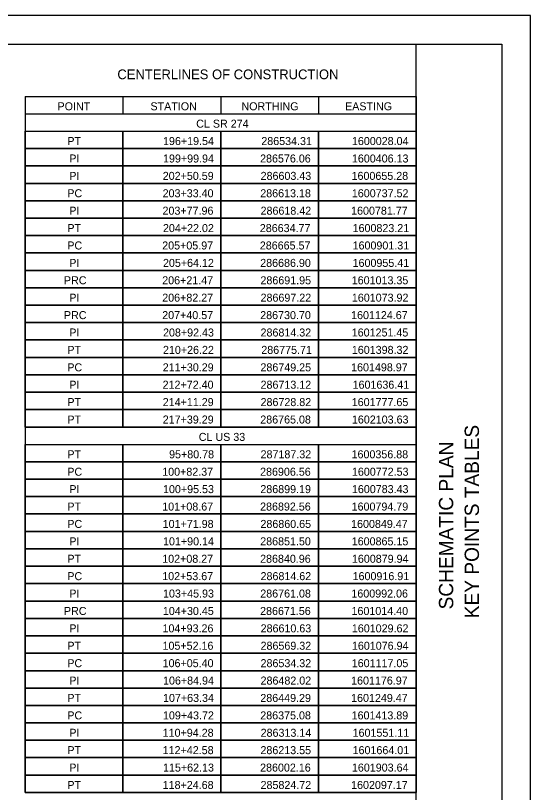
# Model space of a CAD drawing. Extents: x 0 to 34, y 0 to 22.
# Drawn here: x 25 to 34, y 8.41 to 22 of the extents above; entities that cross this region are included whole.
import ezdxf

# ---------------------------------------------------------------- set-up
doc = ezdxf.new("R2010")
doc.units = 0
for name, color, linetype in [('SH_Border', 7, 'Continuous'), ('SH_Cut_Line', 7, 'Continuous'), ('SH_Data', 7, 'Continuous'), ('SH_Text', 7, 'Continuous')]:
    doc.layers.add(name, color=color, linetype=linetype)

msp = doc.modelspace()

# ---------------------------------------------------------------- linework, layer by layer
at = {"layer": 'SH_Border'}
msp.add_line((32, 0.5), (32, 21.5), dxfattribs=at)
msp.add_lwpolyline([(1.5, 21.5), (33.5, 21.5), (33.5, 0.5), (1.5, 0.5)], close=True, dxfattribs=at)
at = {"layer": 'SH_Cut_Line'}
msp.add_lwpolyline([(0, 0), (34, 0), (34, 22), (0, 22)], close=True, dxfattribs=at)
at = {"layer": 'SH_Text'}
for p, q in [((25.169, 20.587), (32, 20.587)), ((25.169, 20.587), (25.169, 19.978)), ((26.877, 20.587), (26.877, 20.283)), ((28.585, 20.587), (28.585, 20.283)), ((30.292, 20.587), (30.292, 20.283)), ((32, 20.587), (32, 19.978)), ((25.169, 20.283), (32, 20.283)), ((25.169, 19.978), (32, 19.978)), ((25.169, 19.978), (25.169, 14.804)), ((26.877, 19.978), (26.877, 14.804)), ((28.585, 19.978), (28.585, 14.804)), ((30.292, 19.978), (30.292, 14.804)), ((32, 19.978), (32, 14.804)), ((25.169, 19.674), (32, 19.674)), ((25.169, 19.37), (32, 19.37)), ((25.169, 19.065), (32, 19.065)), ((25.169, 18.761), (32, 18.761)), ((25.169, 18.457), (32, 18.457)), ((25.169, 18.152), (32, 18.152)), ((25.169, 17.848), (32, 17.848)), ((25.169, 17.543), (32, 17.543)), ((25.169, 17.239), (32, 17.239)), ((25.169, 16.935), (32, 16.935)), ((25.169, 16.63), (32, 16.63)), ((25.169, 16.326), (32, 16.326)), ((25.169, 16.022), (32, 16.022)), ((25.169, 15.717), (32, 15.717)), ((25.169, 15.413), (32, 15.413)), ((25.169, 15.109), (32, 15.109)), ((25.169, 14.804), (32, 14.804)), ((25.169, 14.804), (25.169, 14.5)), ((32, 14.804), (32, 14.5)), ((25.169, 14.5), (32, 14.5)), ((25.169, 14.5), (25.169, 8.413)), ((26.877, 14.5), (26.877, 8.413)), ((28.585, 14.5), (28.585, 8.413)), ((30.292, 14.5), (30.292, 8.413)), ((32, 14.5), (32, 8.413)), ((25.169, 14.196), (32, 14.196)), ((25.169, 13.891), (32, 13.891)), ((25.169, 13.587), (32, 13.587)), ((25.169, 13.283), (32, 13.283)), ((25.169, 12.978), (32, 12.978)), ((25.169, 12.674), (32, 12.674)), ((25.169, 12.37), (32, 12.37)), ((25.169, 12.065), (32, 12.065)), ((25.169, 11.761), (32, 11.761)), ((25.169, 11.457), (32, 11.457)), ((25.169, 11.152), (32, 11.152)), ((25.169, 10.848), (32, 10.848)), ((25.169, 10.543), (32, 10.543)), ((25.169, 10.239), (32, 10.239)), ((25.169, 9.935), (32, 9.935)), ((25.169, 9.63), (32, 9.63)), ((25.169, 9.326), (32, 9.326)), ((25.169, 9.022), (32, 9.022)), ((25.169, 8.717), (32, 8.717)), ((25.169, 8.413), (32, 8.413))]:
    msp.add_line(p, q, dxfattribs=at)
for points in [[(25.169, 19.978), (26.877, 19.978), (26.877, 19.674), (25.169, 19.674)], [(26.877, 19.978), (28.585, 19.978), (28.585, 19.674), (26.877, 19.674)], [(28.585, 19.978), (30.292, 19.978), (30.292, 19.674), (28.585, 19.674)], [(30.292, 19.978), (32, 19.978), (32, 19.674), (30.292, 19.674)], [(25.169, 19.674), (26.877, 19.674), (26.877, 19.37), (25.169, 19.37)], [(26.877, 19.674), (28.585, 19.674), (28.585, 19.37), (26.877, 19.37)], [(28.585, 19.674), (30.292, 19.674), (30.292, 19.37), (28.585, 19.37)], [(30.292, 19.674), (32, 19.674), (32, 19.37), (30.292, 19.37)], [(25.169, 19.37), (26.877, 19.37), (26.877, 19.065), (25.169, 19.065)], [(26.877, 19.37), (28.585, 19.37), (28.585, 19.065), (26.877, 19.065)], [(28.585, 19.37), (30.292, 19.37), (30.292, 19.065), (28.585, 19.065)], [(30.292, 19.37), (32, 19.37), (32, 19.065), (30.292, 19.065)], [(25.169, 19.065), (26.877, 19.065), (26.877, 18.761), (25.169, 18.761)], [(26.877, 19.065), (28.585, 19.065), (28.585, 18.761), (26.877, 18.761)], [(28.585, 19.065), (30.292, 19.065), (30.292, 18.761), (28.585, 18.761)], [(30.292, 19.065), (32, 19.065), (32, 18.761), (30.292, 18.761)], [(25.169, 18.761), (26.877, 18.761), (26.877, 18.457), (25.169, 18.457)], [(26.877, 18.761), (28.585, 18.761), (28.585, 18.457), (26.877, 18.457)], [(28.585, 18.761), (30.292, 18.761), (30.292, 18.457), (28.585, 18.457)], [(30.292, 18.761), (32, 18.761), (32, 18.457), (30.292, 18.457)], [(25.169, 18.457), (26.877, 18.457), (26.877, 18.152), (25.169, 18.152)], [(26.877, 18.457), (28.585, 18.457), (28.585, 18.152), (26.877, 18.152)], [(28.585, 18.457), (30.292, 18.457), (30.292, 18.152), (28.585, 18.152)], [(30.292, 18.457), (32, 18.457), (32, 18.152), (30.292, 18.152)], [(25.169, 18.152), (26.877, 18.152), (26.877, 17.848), (25.169, 17.848)], [(26.877, 18.152), (28.585, 18.152), (28.585, 17.848), (26.877, 17.848)], [(28.585, 18.152), (30.292, 18.152), (30.292, 17.848), (28.585, 17.848)], [(30.292, 18.152), (32, 18.152), (32, 17.848), (30.292, 17.848)], [(25.169, 17.848), (26.877, 17.848), (26.877, 17.543), (25.169, 17.543)], [(26.877, 17.848), (28.585, 17.848), (28.585, 17.543), (26.877, 17.543)], [(28.585, 17.848), (30.292, 17.848), (30.292, 17.543), (28.585, 17.543)], [(30.292, 17.848), (32, 17.848), (32, 17.543), (30.292, 17.543)], [(25.169, 17.543), (26.877, 17.543), (26.877, 17.239), (25.169, 17.239)], [(26.877, 17.543), (28.585, 17.543), (28.585, 17.239), (26.877, 17.239)], [(28.585, 17.543), (30.292, 17.543), (30.292, 17.239), (28.585, 17.239)], [(30.292, 17.543), (32, 17.543), (32, 17.239), (30.292, 17.239)], [(25.169, 17.239), (26.877, 17.239), (26.877, 16.935), (25.169, 16.935)], [(26.877, 17.239), (28.585, 17.239), (28.585, 16.935), (26.877, 16.935)], [(28.585, 17.239), (30.292, 17.239), (30.292, 16.935), (28.585, 16.935)], [(30.292, 17.239), (32, 17.239), (32, 16.935), (30.292, 16.935)], [(25.169, 16.935), (26.877, 16.935), (26.877, 16.63), (25.169, 16.63)], [(26.877, 16.935), (28.585, 16.935), (28.585, 16.63), (26.877, 16.63)], [(28.585, 16.935), (30.292, 16.935), (30.292, 16.63), (28.585, 16.63)], [(30.292, 16.935), (32, 16.935), (32, 16.63), (30.292, 16.63)], [(25.169, 16.63), (26.877, 16.63), (26.877, 16.326), (25.169, 16.326)], [(26.877, 16.63), (28.585, 16.63), (28.585, 16.326), (26.877, 16.326)], [(28.585, 16.63), (30.292, 16.63), (30.292, 16.326), (28.585, 16.326)], [(30.292, 16.63), (32, 16.63), (32, 16.326), (30.292, 16.326)], [(25.169, 16.326), (26.877, 16.326), (26.877, 16.022), (25.169, 16.022)], [(26.877, 16.326), (28.585, 16.326), (28.585, 16.022), (26.877, 16.022)], [(28.585, 16.326), (30.292, 16.326), (30.292, 16.022), (28.585, 16.022)], [(30.292, 16.326), (32, 16.326), (32, 16.022), (30.292, 16.022)], [(25.169, 16.022), (26.877, 16.022), (26.877, 15.717), (25.169, 15.717)], [(26.877, 16.022), (28.585, 16.022), (28.585, 15.717), (26.877, 15.717)], [(28.585, 16.022), (30.292, 16.022), (30.292, 15.717), (28.585, 15.717)], [(30.292, 16.022), (32, 16.022), (32, 15.717), (30.292, 15.717)], [(25.169, 15.717), (26.877, 15.717), (26.877, 15.413), (25.169, 15.413)], [(26.877, 15.717), (28.585, 15.717), (28.585, 15.413), (26.877, 15.413)], [(28.585, 15.717), (30.292, 15.717), (30.292, 15.413), (28.585, 15.413)], [(30.292, 15.717), (32, 15.717), (32, 15.413), (30.292, 15.413)], [(25.169, 15.413), (26.877, 15.413), (26.877, 15.109), (25.169, 15.109)], [(26.877, 15.413), (28.585, 15.413), (28.585, 15.109), (26.877, 15.109)], [(28.585, 15.413), (30.292, 15.413), (30.292, 15.109), (28.585, 15.109)], [(30.292, 15.413), (32, 15.413), (32, 15.109), (30.292, 15.109)], [(25.169, 15.109), (26.877, 15.109), (26.877, 14.804), (25.169, 14.804)], [(26.877, 15.109), (28.585, 15.109), (28.585, 14.804), (26.877, 14.804)], [(28.585, 15.109), (30.292, 15.109), (30.292, 14.804), (28.585, 14.804)], [(30.292, 15.109), (32, 15.109), (32, 14.804), (30.292, 14.804)], [(25.169, 14.5), (26.877, 14.5), (26.877, 14.196), (25.169, 14.196)], [(26.877, 14.5), (28.585, 14.5), (28.585, 14.196), (26.877, 14.196)], [(28.585, 14.5), (30.292, 14.5), (30.292, 14.196), (28.585, 14.196)], [(30.292, 14.5), (32, 14.5), (32, 14.196), (30.292, 14.196)], [(25.169, 14.196), (26.877, 14.196), (26.877, 13.891), (25.169, 13.891)], [(26.877, 14.196), (28.585, 14.196), (28.585, 13.891), (26.877, 13.891)], [(28.585, 14.196), (30.292, 14.196), (30.292, 13.891), (28.585, 13.891)], [(30.292, 14.196), (32, 14.196), (32, 13.891), (30.292, 13.891)], [(25.169, 13.891), (26.877, 13.891), (26.877, 13.587), (25.169, 13.587)], [(26.877, 13.891), (28.585, 13.891), (28.585, 13.587), (26.877, 13.587)], [(28.585, 13.891), (30.292, 13.891), (30.292, 13.587), (28.585, 13.587)], [(30.292, 13.891), (32, 13.891), (32, 13.587), (30.292, 13.587)], [(25.169, 13.587), (26.877, 13.587), (26.877, 13.283), (25.169, 13.283)], [(26.877, 13.587), (28.585, 13.587), (28.585, 13.283), (26.877, 13.283)], [(28.585, 13.587), (30.292, 13.587), (30.292, 13.283), (28.585, 13.283)], [(30.292, 13.587), (32, 13.587), (32, 13.283), (30.292, 13.283)], [(25.169, 13.283), (26.877, 13.283), (26.877, 12.978), (25.169, 12.978)], [(26.877, 13.283), (28.585, 13.283), (28.585, 12.978), (26.877, 12.978)], [(28.585, 13.283), (30.292, 13.283), (30.292, 12.978), (28.585, 12.978)], [(30.292, 13.283), (32, 13.283), (32, 12.978), (30.292, 12.978)], [(25.169, 12.978), (26.877, 12.978), (26.877, 12.674), (25.169, 12.674)], [(26.877, 12.978), (28.585, 12.978), (28.585, 12.674), (26.877, 12.674)], [(28.585, 12.978), (30.292, 12.978), (30.292, 12.674), (28.585, 12.674)], [(30.292, 12.978), (32, 12.978), (32, 12.674), (30.292, 12.674)], [(25.169, 12.674), (26.877, 12.674), (26.877, 12.37), (25.169, 12.37)], [(26.877, 12.674), (28.585, 12.674), (28.585, 12.37), (26.877, 12.37)], [(28.585, 12.674), (30.292, 12.674), (30.292, 12.37), (28.585, 12.37)], [(30.292, 12.674), (32, 12.674), (32, 12.37), (30.292, 12.37)], [(25.169, 12.37), (26.877, 12.37), (26.877, 12.065), (25.169, 12.065)], [(26.877, 12.37), (28.585, 12.37), (28.585, 12.065), (26.877, 12.065)], [(28.585, 12.37), (30.292, 12.37), (30.292, 12.065), (28.585, 12.065)], [(30.292, 12.37), (32, 12.37), (32, 12.065), (30.292, 12.065)], [(25.169, 12.065), (26.877, 12.065), (26.877, 11.761), (25.169, 11.761)], [(26.877, 12.065), (28.585, 12.065), (28.585, 11.761), (26.877, 11.761)], [(28.585, 12.065), (30.292, 12.065), (30.292, 11.761), (28.585, 11.761)], [(30.292, 12.065), (32, 12.065), (32, 11.761), (30.292, 11.761)], [(25.169, 11.761), (26.877, 11.761), (26.877, 11.457), (25.169, 11.457)], [(26.877, 11.761), (28.585, 11.761), (28.585, 11.457), (26.877, 11.457)], [(28.585, 11.761), (30.292, 11.761), (30.292, 11.457), (28.585, 11.457)], [(30.292, 11.761), (32, 11.761), (32, 11.457), (30.292, 11.457)], [(25.169, 11.457), (26.877, 11.457), (26.877, 11.152), (25.169, 11.152)], [(26.877, 11.457), (28.585, 11.457), (28.585, 11.152), (26.877, 11.152)], [(28.585, 11.457), (30.292, 11.457), (30.292, 11.152), (28.585, 11.152)], [(30.292, 11.457), (32, 11.457), (32, 11.152), (30.292, 11.152)], [(25.169, 11.152), (26.877, 11.152), (26.877, 10.848), (25.169, 10.848)], [(26.877, 11.152), (28.585, 11.152), (28.585, 10.848), (26.877, 10.848)], [(28.585, 11.152), (30.292, 11.152), (30.292, 10.848), (28.585, 10.848)], [(30.292, 11.152), (32, 11.152), (32, 10.848), (30.292, 10.848)], [(25.169, 10.848), (26.877, 10.848), (26.877, 10.543), (25.169, 10.543)], [(26.877, 10.848), (28.585, 10.848), (28.585, 10.543), (26.877, 10.543)], [(28.585, 10.848), (30.292, 10.848), (30.292, 10.543), (28.585, 10.543)], [(30.292, 10.848), (32, 10.848), (32, 10.543), (30.292, 10.543)], [(25.169, 10.543), (26.877, 10.543), (26.877, 10.239), (25.169, 10.239)], [(26.877, 10.543), (28.585, 10.543), (28.585, 10.239), (26.877, 10.239)], [(28.585, 10.543), (30.292, 10.543), (30.292, 10.239), (28.585, 10.239)], [(30.292, 10.543), (32, 10.543), (32, 10.239), (30.292, 10.239)], [(25.169, 10.239), (26.877, 10.239), (26.877, 9.935), (25.169, 9.935)], [(26.877, 10.239), (28.585, 10.239), (28.585, 9.935), (26.877, 9.935)], [(28.585, 10.239), (30.292, 10.239), (30.292, 9.935), (28.585, 9.935)], [(30.292, 10.239), (32, 10.239), (32, 9.935), (30.292, 9.935)], [(25.169, 9.935), (26.877, 9.935), (26.877, 9.63), (25.169, 9.63)], [(26.877, 9.935), (28.585, 9.935), (28.585, 9.63), (26.877, 9.63)], [(28.585, 9.935), (30.292, 9.935), (30.292, 9.63), (28.585, 9.63)], [(30.292, 9.935), (32, 9.935), (32, 9.63), (30.292, 9.63)], [(25.169, 9.63), (26.877, 9.63), (26.877, 9.326), (25.169, 9.326)], [(26.877, 9.63), (28.585, 9.63), (28.585, 9.326), (26.877, 9.326)], [(28.585, 9.63), (30.292, 9.63), (30.292, 9.326), (28.585, 9.326)], [(30.292, 9.63), (32, 9.63), (32, 9.326), (30.292, 9.326)], [(25.169, 9.326), (26.877, 9.326), (26.877, 9.022), (25.169, 9.022)], [(26.877, 9.326), (28.585, 9.326), (28.585, 9.022), (26.877, 9.022)], [(28.585, 9.326), (30.292, 9.326), (30.292, 9.022), (28.585, 9.022)], [(30.292, 9.326), (32, 9.326), (32, 9.022), (30.292, 9.022)], [(25.169, 9.022), (26.877, 9.022), (26.877, 8.717), (25.169, 8.717)], [(26.877, 9.022), (28.585, 9.022), (28.585, 8.717), (26.877, 8.717)], [(28.585, 9.022), (30.292, 9.022), (30.292, 8.717), (28.585, 8.717)], [(30.292, 9.022), (32, 9.022), (32, 8.717), (30.292, 8.717)], [(25.169, 8.717), (26.877, 8.717), (26.877, 8.413), (25.169, 8.413)], [(26.877, 8.717), (28.585, 8.717), (28.585, 8.413), (26.877, 8.413)], [(28.585, 8.717), (30.292, 8.717), (30.292, 8.413), (28.585, 8.413)], [(30.292, 8.717), (32, 8.717), (32, 8.413), (30.292, 8.413)]]:
    msp.add_lwpolyline(points, close=True, dxfattribs=at)

# ---------------------------------------------------------------- texts
at = {"layer": 'SH_Data'}
for s, p in [('KEY POINTS TABLES', (33.1, 11.46)), ('SCHEMATIC PLAN', (32.65, 11.614))]:
    msp.add_text(s, height=0.25, rotation=90, dxfattribs=at).set_placement(p)
at = {"layer": 'SH_Text'}
for s, height, p in [('CENTERLINES OF CONSTRUCTION', 0.17, (26.779, 20.887)), ('POINT', 0.14, (25.733, 20.343)), ('STATION', 0.14, (27.357, 20.343)), ('NORTHING', 0.14, (28.948, 20.343)), ('EASTING', 0.14, (30.759, 20.343)), ('CL SR 274', 0.14, (28.157, 20.039)), ('PT', 0.14, (25.905, 19.735)), ('196+19.54', 0.14, (27.577, 19.735)), ('286534.31', 0.14, (29.295, 19.735)), ('1600028.04', 0.14, (30.879, 19.735)), ('PI', 0.14, (25.939, 19.43)), ('199+99.94', 0.14, (27.577, 19.43)), ('286576.06', 0.14, (29.274, 19.43)), ('1600406.13', 0.14, (30.879, 19.43)), ('PI', 0.14, (25.939, 19.126)), ('202+50.59', 0.14, (27.572, 19.126)), ('286603.43', 0.14, (29.283, 19.126)), ('1600655.28', 0.14, (30.873, 19.126)), ('PC', 0.14, (25.904, 18.822)), ('203+33.40', 0.14, (27.57, 18.822)), ('286613.18', 0.14, (29.277, 18.822)), ('1600737.52', 0.14, (30.878, 18.822)), ('PI', 0.14, (25.939, 18.517)), ('203+77.96', 0.14, (27.568, 18.517)), ('286618.42', 0.14, (29.282, 18.517)), ('1600781.77', 0.14, (30.865, 18.517)), ('PT', 0.14, (25.905, 18.213)), ('204+22.02', 0.14, (27.576, 18.213)), ('286634.77', 0.14, (29.269, 18.213)), ('1600823.21', 0.14, (30.891, 18.213)), ('PC', 0.14, (25.904, 17.909)), ('205+05.97', 0.14, (27.563, 17.909)), ('286665.57', 0.14, (29.269, 17.909)), ('1600901.31', 0.14, (30.891, 17.909)), ('PI', 0.14, (25.939, 17.604)), ('205+64.12', 0.14, (27.576, 17.604)), ('286686.90', 0.14, (29.276, 17.604)), ('1600955.41', 0.14, (30.891, 17.604)), ('PRC', 0.14, (25.845, 17.3)), ('206+21.47', 0.14, (27.563, 17.3)), ('286691.95', 0.14, (29.28, 17.3)), ('1601013.35', 0.14, (30.876, 17.3)), ('PI', 0.14, (25.939, 16.996)), ('206+82.27', 0.14, (27.563, 16.996)), ('286697.22', 0.14, (29.282, 16.996)), ('1601073.92', 0.14, (30.878, 16.996)), ('PRC', 0.14, (25.845, 16.691)), ('207+40.57', 0.14, (27.563, 16.691)), ('286730.70', 0.14, (29.276, 16.691)), ('1601124.67', 0.14, (30.865, 16.691)), ('PI', 0.14, (25.939, 16.387)), ('208+92.43', 0.14, (27.577, 16.387)), ('286814.32', 0.14, (29.282, 16.387)), ('1601251.45', 0.14, (30.876, 16.387)), ('PT', 0.14, (25.905, 16.083)), ('210+26.22', 0.14, (27.576, 16.083)), ('286775.71', 0.14, (29.295, 16.083)), ('1601398.32', 0.14, (30.878, 16.083)), ('PC', 0.14, (25.904, 15.778)), ('211+30.29', 0.14, (27.572, 15.778)), ('286749.25', 0.14, (29.28, 15.778)), ('1601498.97', 0.14, (30.865, 15.778)), ('PI', 0.14, (25.939, 15.474)), ('212+72.40', 0.14, (27.57, 15.474)), ('286713.12', 0.14, (29.282, 15.474)), ('1601636.41', 0.14, (30.891, 15.474)), ('PT', 0.14, (25.905, 15.17)), ('214+11.29', 0.14, (27.572, 15.17)), ('286728.82', 0.14, (29.282, 15.17)), ('1601777.65', 0.14, (30.876, 15.17)), ('PT', 0.14, (25.905, 14.865)), ('217+39.29', 0.14, (27.572, 14.865)), ('286765.08', 0.14, (29.277, 14.865)), ('1602103.63', 0.14, (30.879, 14.865)), ('CL US 33', 0.14, (28.202, 14.561)), ('PT', 0.14, (25.905, 14.257)), ('95+80.78', 0.14, (27.683, 14.257)), ('287187.32', 0.14, (29.282, 14.257)), ('1600356.88', 0.14, (30.873, 14.257)), ('PC', 0.14, (25.904, 13.952)), ('100+82.37', 0.14, (27.563, 13.952)), ('286906.56', 0.14, (29.274, 13.952)), ('1600772.53', 0.14, (30.879, 13.952)), ('PI', 0.14, (25.939, 13.648)), ('100+95.53', 0.14, (27.577, 13.648)), ('286899.19', 0.14, (29.278, 13.648)), ('1600783.43', 0.14, (30.879, 13.648)), ('PT', 0.14, (25.905, 13.343)), ('101+08.67', 0.14, (27.563, 13.343)), ('286892.56', 0.14, (29.274, 13.343)), ('1600794.79', 0.14, (30.874, 13.343)), ('PC', 0.14, (25.904, 13.039)), ('101+71.98', 0.14, (27.571, 13.039)), ('286860.65', 0.14, (29.28, 13.039)), ('1600849.47', 0.14, (30.865, 13.039)), ('PI', 0.14, (25.939, 12.735)), ('101+90.14', 0.14, (27.577, 12.735)), ('286851.50', 0.14, (29.276, 12.735)), ('1600865.15', 0.14, (30.876, 12.735)), ('PT', 0.14, (25.905, 12.43)), ('102+08.27', 0.14, (27.563, 12.43)), ('286840.96', 0.14, (29.274, 12.43)), ('1600879.94', 0.14, (30.879, 12.43)), ('PC', 0.14, (25.904, 12.126)), ('102+53.67', 0.14, (27.563, 12.126)), ('286814.62', 0.14, (29.282, 12.126)), ('1600916.91', 0.14, (30.891, 12.126)), ('PI', 0.14, (25.939, 11.822)), ('103+45.93', 0.14, (27.577, 11.822)), ('286761.08', 0.14, (29.277, 11.822)), ('1600992.06', 0.14, (30.87, 11.822)), ('PRC', 0.14, (25.845, 11.517)), ('104+30.45', 0.14, (27.574, 11.517)), ('286671.56', 0.14, (29.274, 11.517)), ('1601014.40', 0.14, (30.872, 11.517)), ('PI', 0.14, (25.939, 11.213)), ('104+93.26', 0.14, (27.568, 11.213)), ('286610.63', 0.14, (29.283, 11.213)), ('1601029.62', 0.14, (30.878, 11.213)), ('PT', 0.14, (25.905, 10.909)), ('105+52.16', 0.14, (27.568, 10.909)), ('286569.32', 0.14, (29.282, 10.909)), ('1601076.94', 0.14, (30.879, 10.909)), ('PC', 0.14, (25.904, 10.604)), ('106+05.40', 0.14, (27.57, 10.604)), ('286534.32', 0.14, (29.282, 10.604)), ('1601117.05', 0.14, (30.876, 10.604)), ('PI', 0.14, (25.939, 10.3)), ('106+84.94', 0.14, (27.577, 10.3)), ('286482.02', 0.14, (29.282, 10.3)), ('1601176.97', 0.14, (30.865, 10.3)), ('PT', 0.14, (25.905, 9.996)), ('107+63.34', 0.14, (27.577, 9.996)), ('286449.29', 0.14, (29.278, 9.996)), ('1601249.47', 0.14, (30.865, 9.996)), ('PC', 0.14, (25.904, 9.691)), ('109+43.72', 0.14, (27.576, 9.691)), ('286375.08', 0.14, (29.277, 9.691)), ('1601413.89', 0.14, (30.874, 9.691)), ('PI', 0.14, (25.939, 9.387)), ('110+94.28', 0.14, (27.571, 9.387)), ('286313.14', 0.14, (29.283, 9.387)), ('1601551.11', 0.14, (30.891, 9.387)), ('PT', 0.14, (25.905, 9.083)), ('112+42.58', 0.14, (27.571, 9.083)), ('286213.55', 0.14, (29.28, 9.083)), ('1601664.01', 0.14, (30.891, 9.083)), ('PI', 0.14, (25.939, 8.778)), ('115+62.13', 0.14, (27.577, 8.778)), ('286002.16', 0.14, (29.274, 8.778)), ('1601903.64', 0.14, (30.879, 8.778)), ('PT', 0.14, (25.905, 8.474)), ('118+24.68', 0.14, (27.571, 8.474)), ('285824.72', 0.14, (29.282, 8.474)), ('1602097.17', 0.14, (30.865, 8.474))]:
    msp.add_text(s, height=height, dxfattribs=at).set_placement(p)

doc.saveas('drawing.dxf')
